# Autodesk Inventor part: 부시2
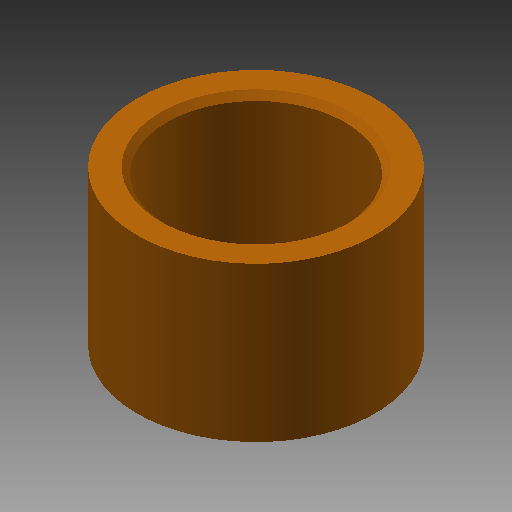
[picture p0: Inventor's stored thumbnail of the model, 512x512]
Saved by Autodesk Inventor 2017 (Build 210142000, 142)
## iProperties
Created: 2016-08
Part Number: 부시2
Material: 강철, 탄소
Document SubType Name: Modeling
Designer: mduedu
Density: 7.87 g/cm^3
Appearance: 주황색
Author: mduedu
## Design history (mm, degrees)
sketch "스케치1"
  geometry: C1 r 7.5 at (0, 0); C2 r 10 at (0, 0); 1 further point
  constraints: 2 centre point, 2 coincident
  dimensions: "d0" = 15 diameter of C1; "d1" = 20 diameter of C2
extrude "돌출1" new body sketch "스케치1" stored distance "d2" = 13; taper "d3" = 0 deg
chamfer "모따기1" distance "d4" = 0.5; stored, may be unused: second distance "d5" = 2, angle "d6" = 45 deg
node "솔리드1"
